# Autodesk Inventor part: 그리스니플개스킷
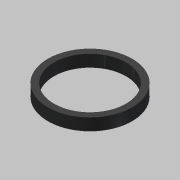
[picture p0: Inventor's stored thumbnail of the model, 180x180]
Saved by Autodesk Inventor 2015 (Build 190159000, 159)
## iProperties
Created: 2019-05
Part Number: 그리스니플개스킷
Material: 고무
Document SubType Name: Modeling
Designer: mduedu
Density: 1 g/cm^3
Appearance: 고무 - 검은색 - 버전 1.1
Author: mduedu
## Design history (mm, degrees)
sketch "스케치1"
  geometry: C1 r 3 at (0, 0); C2 r 3.5 at (0, 0); 1 further point
  constraints: 2 centre point, 2 coincident
  dimensions: "d0" = 6 diameter of C1; "d1" = 7 diameter of C2
extrude "돌출1" new body sketch "스케치1" distance "d2" = 1; taper "d3" = 0 deg
node "솔리드1"
